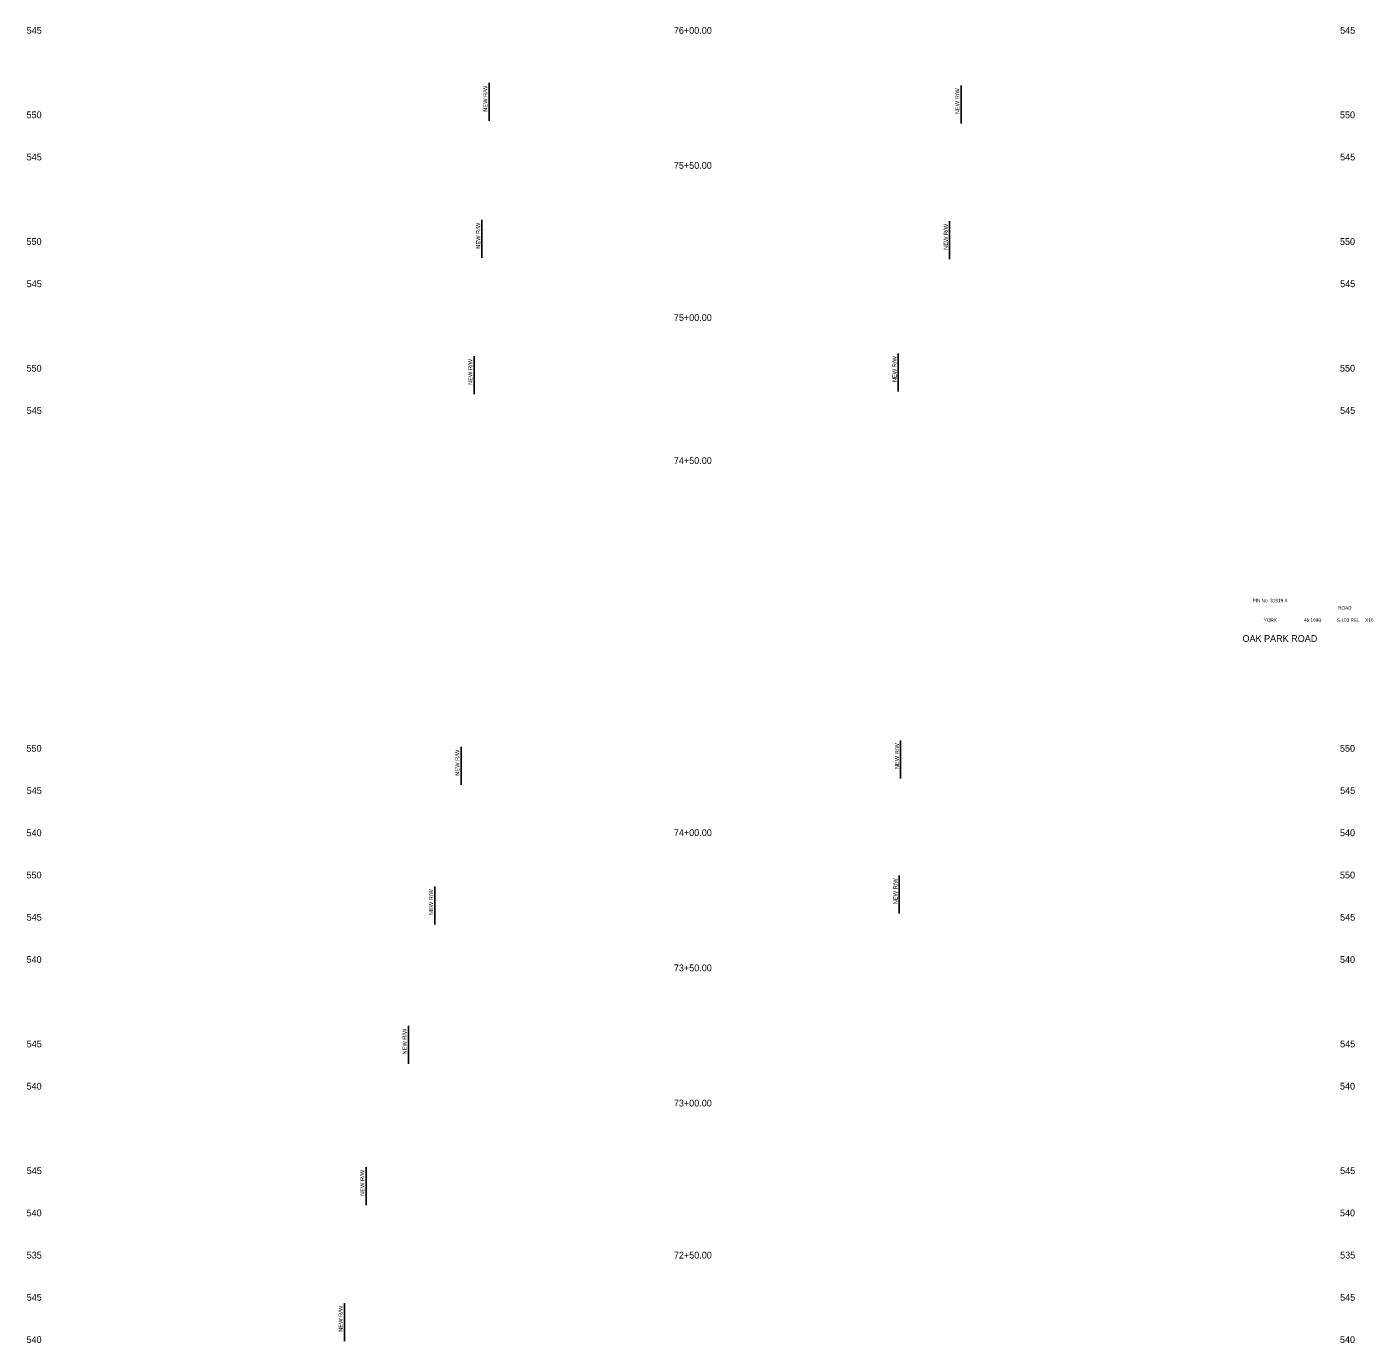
# Model space of a CAD drawing. Extents: x 1001 to 1161, y 1005 to 3518.
# Drawn here: x 1001.2 to 1160.6, y 2740.1 to 2895.9 of the extents above; entities that cross this region are included whole.
import ezdxf

# ---------------------------------------------------------------- set-up
doc = ezdxf.new("R2010")
doc.units = 0
for name, color, linetype in [('RD_SHT_TX', 7, 'Continuous'), ('RD_XS_NewRW', 7, 'Continuous'), ('RD_XS_TX_Elev_EX', 7, 'Continuous'), ('RD_XS_TX_Station', 7, 'Continuous')]:
    doc.layers.add(name, color=color, linetype=linetype)

msp = doc.modelspace()

# ---------------------------------------------------------------- linework, layer by layer
at = {"layer": 'RD_XS_NewRW'}
for p, q in [((1055.9, 2889.27), (1055.9, 2884.77)), ((1111.79, 2888.97), (1111.79, 2884.47)), ((1055.05, 2873.05), (1055.05, 2868.55)), ((1110.43, 2872.91), (1110.43, 2868.41)), ((1054.12, 2856.93), (1054.12, 2852.43)), ((1104.35, 2857.26), (1104.35, 2852.76)), ((1104.63, 2811.44), (1104.63, 2806.94)), ((1052.58, 2810.66), (1052.58, 2806.16)), ((1049.48, 2794.15), (1049.48, 2789.65)), ((1104.46, 2795.44), (1104.46, 2790.94)), ((1046.35, 2777.64), (1046.35, 2773.14)), ((1041.34, 2760.92), (1041.34, 2756.42)), ((1038.78, 2744.83), (1038.78, 2740.33))]:
    msp.add_line(p, q, dxfattribs=at)

# ---------------------------------------------------------------- texts
at = {"layer": 'RD_SHT_TX'}
for s, height, p in [('PIN No. 31919 X', 0.4, (1146.29, 2827.8)), ('ROAD', 0.4, (1156.41, 2826.93)), ('YORK', 0.4, (1147.61, 2825.48)), ('46.169B', 0.4, (1152.37, 2825.48)), ('S-103 REL', 0.4, (1156.26, 2825.48)), ('X16', 0.4, (1159.63, 2825.48)), ('OAK PARK ROAD', 0.8, (1145.1, 2823.1))]:
    msp.add_text(s, height=height, dxfattribs=at).set_placement(p)
at = {"layer": 'RD_XS_NewRW'}
for p in [(1055.7, 2885.87), (1111.58, 2885.58), (1054.85, 2869.65), (1110.23, 2869.51), (1053.92, 2853.53), (1104.15, 2853.86), (1052.38, 2807.26), (1104.43, 2808.04), (1104.26, 2792.04), (1049.28, 2790.75), (1046.15, 2774.25), (1041.13, 2757.52), (1038.58, 2741.43)]:
    msp.add_text('NEW R/W ', height=0.488, rotation=90, dxfattribs=at).set_placement(p)
at = {"layer": 'RD_XS_TX_Elev_EX'}
for s, p in [('545', (1001.16, 2895.1)), ('545', (1156.66, 2895.1)), ('550', (1001.14, 2885.1)), ('550', (1156.64, 2885.1)), ('545', (1001.16, 2880.1)), ('545', (1156.66, 2880.1)), ('550', (1001.14, 2870.1)), ('550', (1156.64, 2870.1)), ('545', (1001.16, 2865.1)), ('545', (1156.66, 2865.1)), ('550', (1001.14, 2855.1)), ('550', (1156.64, 2855.1)), ('545', (1001.16, 2850.1)), ('545', (1156.66, 2850.1)), ('550', (1001.14, 2810.1)), ('550', (1156.64, 2810.1)), ('545', (1001.16, 2805.1)), ('545', (1156.66, 2805.1)), ('540', (1001.14, 2800.1)), ('540', (1156.64, 2800.1)), ('550', (1001.14, 2795.1)), ('550', (1156.64, 2795.1)), ('545', (1001.16, 2790.1)), ('545', (1156.66, 2790.1)), ('540', (1001.14, 2785.1)), ('540', (1156.64, 2785.1)), ('545', (1001.16, 2775.1)), ('545', (1156.66, 2775.1)), ('540', (1001.14, 2770.1)), ('540', (1156.64, 2770.1)), ('545', (1001.16, 2760.1)), ('545', (1156.66, 2760.1)), ('540', (1001.14, 2755.1)), ('540', (1156.64, 2755.1)), ('535', (1001.16, 2750.1)), ('535', (1156.66, 2750.1)), ('545', (1001.16, 2745.1)), ('545', (1156.66, 2745.1)), ('540', (1001.14, 2740.1)), ('540', (1156.64, 2740.1))]:
    msp.add_text(s, height=0.8, dxfattribs=at).set_placement(p)
at = {"layer": 'RD_XS_TX_Station'}
for s, p in [('76+00.00', (1077.78, 2895.09)), ('75+50.00', (1077.78, 2879.11)), ('75+00.00', (1077.78, 2861.1)), ('74+50.00', (1077.78, 2844.17)), ('74+00.00', (1077.78, 2800.12)), ('73+50.00', (1077.78, 2784.11)), ('73+00.00', (1077.78, 2768.1)), ('72+50.00', (1077.78, 2750.1))]:
    msp.add_text(s, height=0.8, dxfattribs=at).set_placement(p)

doc.saveas('drawing.dxf')
